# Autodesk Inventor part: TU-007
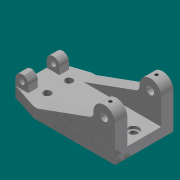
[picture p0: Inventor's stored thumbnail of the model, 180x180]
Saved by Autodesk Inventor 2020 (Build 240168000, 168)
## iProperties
Created: 2008-07
Part Number: TU-007
Document SubType Name: Modeling
Designer: PN
Density: 7.75 g/cm^3
Material: Stainless Steel, 440C
Description: Cylinder Base
Mass: 2332.18 g
Surface Area: 522.777 cm^2
Volume: 300.927 cm^3
Appearance: Steel
Author: PN
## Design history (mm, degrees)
sketch "Sketch1"
  geometry: L1 (0, 0)-(-160, 0); L2 (-160, 0)-(-160, 86); L3 (-160, 86)-(0, 86); L4 (0, 86)-(0, 0)
  constraints: 8 end point, 2 parallel, 1 horizontal, 1 perpendicular
  dimensions: "d0" = 160 distance of L1.start L1.end; "d1" = 86 distance of L3.end L1.start
extrude "Extrusion1" new body sketch "Sketch1" distance "d2" = 15; taper "d3" = 0 deg
sketch "Sketch2"
  geometry: L1 (160, 15)-(0, 15) reference; L2 (160, 0)-(0, 0) reference; L3 (160, 0)-(160, 15) reference; L4 (160, 15)-(160, 53); L5 (128, 53)-(128, 45); L6 (128, 45)-(45.576, 15); A1 r 16 centre (144, 53) between (160, 53) and (128, 53)
  constraints: 6 end point, 2 point on circle, 2 tangent, 1 centre point, 1 collinear, 1 parallel, 1 point on line
  dimensions: "d4" = 16 radius of A1; "d5" = 53 distance from line of A1.centre L2; "d6" = 20 deg angle of L1 L6; "d7" = 8 distance of L5.start L5.end
extrude "Extrusion2" join sketch "Sketch2" distance "d8" = 18; taper "d9" = 0 deg
fillet "Fillet1" dims "d19" = 8
hole "Hole1" diameter "d12" = 11; stored, may be unused: countersink angle "d16" = 90 deg, drill point angle "d18" = 118 deg; dims "d10" = 10, "d11" = 10, "d13" = 6, "d14" = 4, "d15" = 2, "d17" = 8
workplane "Work Plane1"
mirror "Mirror1"
workplane "Work Plane2"
sketch "Sketch3"
  geometry: L1 (45.576, 15)-(0, 15) reference; L2 (0, 15)-(0, 25); L3 (19, 25)-(19, 15); L4 (160, 0)-(0, 0) reference; A1 r 9.5 centre (9.5, 25) between (19, 25) and (0, 25)
  constraints: 4 end point, 2 perpendicular, 2 point on circle, 2 tangent, 1 centre point, 1 point on line
  dimensions: "d21" = 9.5 radius of A1; "d22" = 25 distance from line of A1.centre L4
extrude "Extrusion3" join sketch "Sketch3" distance "d23" = 14; taper "d24" = 0 deg
hole "Hole2" diameter "d27" = 8; stored, may be unused: countersink angle "d31" = 90 deg, drill point angle "d33" = 118 deg; dims "d25" = 10, "d26" = 10, "d28" = 6, "d29" = 4, "d30" = 2, "d32" = 8
mirror "Mirror2"
chamfer "Chamfer1" distance "d34" = 13; stored, may be unused: second distance "d35" = 40, angle "d36" = 45 deg
chamfer "Chamfer2" distance "d37" = 13; stored, may be unused: second distance "d38" = 40, angle "d39" = 45 deg
workplane "Work Plane3"
sketch "Sketch4"
  geometry: L1 (-16, 18)-(16, 18) reference; L2 (-16, 0)-(16, 0) reference; L3 (-16, 68)-(16, 68) reference; L4 (-16, 86)-(16, 86) reference; L5 (0, 86)-(0, 68); L6 (0, 18)-(0, 0); 2 further points
  constraints: 6 midpoint, 4 end point
hole "Hole3" sketch "Sketch4" at (0, 77), (0, 9) diameter "d40" = 4.917; stored, may be unused: countersink angle "d44" = 90 deg, drill point angle "d46" = 118 deg; dims "d41" = 6, "d42" = 4, "d43" = 2, "d45" = 8
sketch "Sketch5"
  geometry: L1 (-160, 27)-(-160, 59) reference; L2 (32, 43)-(-192, 43) reference; 3 further points
  constraints: 1 vertical alignment
  dimensions: "d47" = 16 distance from line of point (-127, 59) L2; "d48" = 32 distance of point (-127, 27) point (-127, 59) (= 2 x d47); "d49" = 33 distance from line of point (-127, 27) L1
hole "Hole4" sketch "Sketch5" at (-127, 59), (-127, 27) diameter "d50" = 11; stored, may be unused: countersink angle "d54" = 90 deg, drill point angle "d56" = 118 deg; dims "d51" = 6, "d52" = 4, "d53" = 2, "d55" = 8
sketch "Sketch6"
  geometry: L1 (0, 68)-(0, 18) reference; L2 (-120, 86)-(-114.424, 86) reference; L3 (0, 43)-(-16, 43); 1 further point
  constraints: 2 end point, 1 midpoint, 1 parallel
  dimensions: "d57" = 16 distance of L3.start L3.end
hole "Hole5" sketch "Sketch6" at (-16, 43) diameter "d58" = 11; stored, may be unused: countersink angle "d62" = 90 deg, drill point angle "d64" = 118 deg; dims "d59" = 6, "d60" = 16, "d61" = 4, "d63" = 8
body "Solid1"
